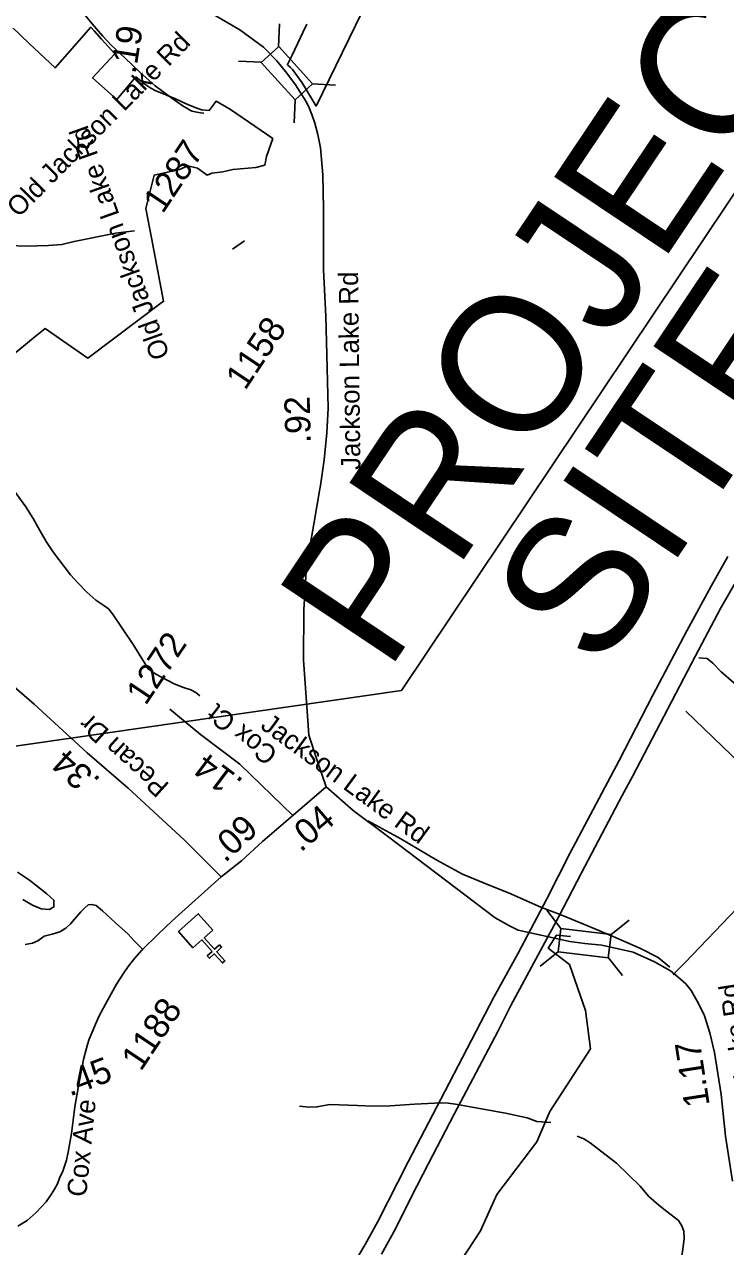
# Model space of a CAD drawing. Extents: x 1715610 to 1720914, y 798298 to 802505.
# Drawn here: x 1715979.8 to 1716054.7, y 799574.8 to 799705.3 of the extents above; entities that cross this region are included whole.
import ezdxf

# ---------------------------------------------------------------- set-up
doc = ezdxf.new("R2010")
doc.units = 0
doc.layers.add('Default', color=7, linetype='Continuous')
doc.layers.add('Prop DSN Text', color=7, linetype='Continuous')

msp = doc.modelspace()

# ---------------------------------------------------------------- linework, layer by layer
at = {"layer": 'Default'}
for p, q in [((1716006.94, 799702.94), (1716007.06, 799705.4)), ((1716005.12, 799701.29), (1716002.66, 799701.41)), ((1716013.05, 799698.85), (1716010.59, 799698.98)), ((1716008.61, 799694.83), (1716008.73, 799697.28)), ((1716002.03, 799681.34), (1716003.31, 799682.21)), ((1716012.04, 799623.88), (1716008.47, 799620.83)), ((1716037.02, 799610.25), (1716035.04, 799610.99)), ((1716035.59, 799610.71), (1716037.11, 799608.77)), ((1716042.47, 799608.12), (1716044.4, 799609.64)), ((1716034.88, 799604.75), (1716036.82, 799606.27)), ((1716042.17, 799605.68), (1716043.7, 799603.74))]:
    msp.add_line(p, q, dxfattribs=at)
for points in [[(1715984, 799710.04), (1715991.9, 799708.62), (1715997.87, 799707.36), (1715999.57, 799706.64), (1716002.83, 799704.77), (1716005.36, 799702.91), (1716006.78, 799701.45), (1716007.85, 799700.13)], [(1715984, 799710.04), (1715984.76, 799708.52), (1715985.92, 799706.77), (1715987.04, 799705.38), (1715988.17, 799704.06), (1715989.03, 799703.15), (1715990.57, 799701.72), (1715992.13, 799700.23), (1715993.78, 799698.78), (1715995.56, 799697.45), (1715996.77, 799696.6), (1715997.14, 799696.37), (1715997.47, 799696.18), (1715997.72, 799696.07), (1715998.06, 799695.98), (1715998.63, 799695.87), (1715998.96, 799695.84)], [(1716016.56, 799708.09), (1716010.96, 799696.6), (1716009.47, 799699.1), (1716008.43, 799700.5), (1716008.19, 799700.75), (1716007.95, 799700.99), (1716007.9, 799701.04), (1716008.39, 799702.06), (1716009.84, 799705.09), (1716009.96, 799705.33), (1716009.92, 799705.37)], [(1716016.56, 799708.09), (1716010.96, 799696.6), (1716009.47, 799699.1), (1716008.43, 799700.5), (1716008.19, 799700.75), (1716007.95, 799700.99), (1716007.9, 799701.04), (1716008.39, 799702.06), (1716009.84, 799705.09), (1716009.96, 799705.33), (1716009.92, 799705.37)], [(1715974.84, 799666.96), (1715980.75, 799671.8), (1715982.04, 799672.85), (1715983.93, 799671.53), (1715986.57, 799669.69), (1715994.67, 799675.76), (1715993.37, 799682.53), (1715992.78, 799685.66), (1715993.68, 799689.23), (1715996.38, 799689.83), (1715997.28, 799690.24), (1715998.3, 799689.98), (1715999.33, 799689.24), (1715999.84, 799689.46), (1716000.99, 799689.6), (1716002.07, 799689.83), (1716004.54, 799690.03), (1716005.47, 799690.31), (1716005.65, 799691.24), (1716006.34, 799693.14), (1716001.83, 799696.23), (1716000.28, 799697.13), (1715999.55, 799696.15), (1715998.74, 799696.19), (1715998.16, 799696.42), (1715997.34, 799696.74), (1715996.62, 799697.06), (1715995.79, 799697.44), (1715995.24, 799697.68), (1715994.68, 799697.91), (1715993.84, 799698.25), (1715993.3, 799698.52), (1715992.67, 799698.96), (1715992.07, 799699.43), (1715991.72, 799699.73), (1715989.67, 799697.3), (1715987.09, 799699.64), (1715989.45, 799702.19), (1715988.06, 799703.74), (1715987.26, 799704.64), (1715986.91, 799705.03), (1715984.37, 799702.15), (1715983.08, 799700.68), (1715980.31, 799703.3), (1715976.56, 799706.89)], [(1715974.84, 799666.96), (1715980.75, 799671.8), (1715982.04, 799672.85), (1715983.93, 799671.53), (1715986.57, 799669.69), (1715994.67, 799675.76), (1715993.37, 799682.53), (1715992.78, 799685.66), (1715993.68, 799689.23), (1715996.38, 799689.83), (1715997.28, 799690.24), (1715998.3, 799689.98), (1715999.33, 799689.24), (1715999.84, 799689.46), (1716000.99, 799689.6), (1716002.07, 799689.83), (1716004.54, 799690.03), (1716005.47, 799690.31), (1716005.65, 799691.24), (1716006.34, 799693.14), (1716001.83, 799696.23), (1716000.28, 799697.13), (1715999.55, 799696.15), (1715998.74, 799696.19), (1715998.16, 799696.42), (1715997.34, 799696.74), (1715996.62, 799697.06), (1715995.79, 799697.44), (1715995.24, 799697.68), (1715994.68, 799697.91), (1715993.84, 799698.25), (1715993.3, 799698.52), (1715992.67, 799698.96), (1715992.07, 799699.43), (1715991.72, 799699.73), (1715989.67, 799697.3), (1715987.09, 799699.64), (1715989.45, 799702.19), (1715988.06, 799703.74), (1715987.26, 799704.64), (1715986.91, 799705.03), (1715984.37, 799702.15), (1715983.08, 799700.68), (1715980.31, 799703.3), (1715976.56, 799706.89)], [(1716007.85, 799700.13), (1716008.76, 799698.86), (1716009.95, 799697.02), (1716010.23, 799696.41), (1716010.51, 799695.71), (1716010.84, 799694.78), (1716011.16, 799693.58), (1716011.42, 799692.15), (1716011.67, 799689.25), (1716011.75, 799685.64), (1716011.75, 799679.11), (1716011.99, 799674.17), (1716012.1, 799670.04), (1716012.24, 799664.35), (1716012.09, 799661.71), (1716011.82, 799658.82), (1716011.42, 799656.09), (1716011.34, 799655.51), (1716010.77, 799652.18), (1716009.93, 799647.45), (1716009.66, 799642.81), (1716009.62, 799637.46), (1716010.12, 799630.45), (1716010.19, 799629.42), (1716011.06, 799626.7), (1716012.04, 799623.88)], [(1715991.55, 799683.28), (1715989.54, 799683.03), (1715985.13, 799682.14), (1715983.82, 799681.83), (1715982.37, 799681.71), (1715981.18, 799681.67), (1715980, 799681.64), (1715978.17, 799681.73)], [(1716036.89, 799610.04), (1716039.32, 799614.69), (1716043.63, 799622.97), (1716044.75, 799625.01), (1716051.48, 799637.87), (1716054.16, 799642.95), (1716057.17, 799648.22), (1716059.03, 799651.06), (1716060.98, 799653.91), (1716062.54, 799656.07), (1716064.21, 799658.15), (1716065.88, 799660.11), (1716066.95, 799661.23), (1716069.27, 799663.67), (1716071.26, 799665.7), (1716071.99, 799666.34), (1716073.29, 799667.48), (1716074.26, 799668.3)], [(1715977.93, 799656.71), (1715978.93, 799655.23), (1715979.95, 799653.8), (1715980.75, 799652.57), (1715981.45, 799651.29), (1715982.12, 799650.11), (1715982.9, 799648.94), (1715984.73, 799646.53), (1715985.55, 799645.65), (1715986.49, 799644.7), (1715987.43, 799643.84), (1715988.29, 799643.25), (1715988.79, 799642.91), (1715989.21, 799642.36), (1715991.42, 799639.11), (1715992.82, 799636.84), (1715993.04, 799636.48), (1715993.83, 799635.94), (1715995.81, 799634.9), (1715996.8, 799634.49), (1715997.59, 799634.27), (1715998.12, 799633.96), (1715998.56, 799633.6)], [(1716014.52, 799572.21), (1716016.2, 799575.02), (1716017.53, 799577.4), (1716020.78, 799583.82), (1716024.71, 799591.36), (1716029.94, 799601.43), (1716032.55, 799606.11), (1716035.6, 799611.94), (1716038.09, 799616.83), (1716043.32, 799626.71), (1716046.93, 799633.67), (1716050.56, 799640.56), (1716053.15, 799645.31), (1716054.95, 799648.5)], [(1716000.83, 799614.29), (1715996.86, 799618.22), (1715990.88, 799623.76), (1715986.52, 799627.54), (1715980.85, 799632.71), (1715977.66, 799635.5), (1715973.98, 799639.15), (1715972.22, 799641.35)], [(1716051.83, 799637.68), (1716052.72, 799637.6), (1716053.34, 799637.12), (1716054.21, 799636.16), (1716055.55, 799635.03), (1716057.3, 799633.74), (1716059.46, 799632.26), (1716061.05, 799631.28), (1716062.17, 799630.67), (1716063.1, 799630.19), (1716063.93, 799629.94)], [(1716008.47, 799620.83), (1716002.8, 799626.33), (1715998.61, 799629.47), (1715995.33, 799632.18)], [(1716072.43, 799603.78), (1716068.96, 799606.8), (1716058.23, 799624.46), (1716050.43, 799631.98)], [(1716012.04, 799623.88), (1716014.93, 799621.35), (1716018.6, 799618.63), (1716030.1, 799609.9), (1716031.62, 799609.04), (1716032.55, 799608.59), (1716038.07, 799607.36), (1716039.67, 799607.17)], [(1716008.47, 799620.83), (1716005.25, 799618.05), (1716003.01, 799615.98), (1716000.83, 799614.29)], [(1716035.04, 799610.99), (1716031.76, 799612.46), (1716028.83, 799613.65), (1716026.59, 799614.57), (1716023.86, 799616.06), (1716020.01, 799618.34), (1716016.5, 799620.26)], [(1715979.66, 799611.85), (1715980.68, 799611.27), (1715981.61, 799610.85), (1715982.48, 799610.78), (1715982.97, 799611.06), (1715982.95, 799611.78), (1715982.2, 799612.48), (1715980.34, 799613.93), (1715979.08, 799614.77)], [(1716000.83, 799614.29), (1715997.34, 799611.14), (1715995.54, 799609.53), (1715994.08, 799608.16), (1715992.36, 799606.44), (1715991.55, 799605.57), (1715990.9, 799604.7), (1715990.44, 799604.03), (1715989.66, 799602.81), (1715988.67, 799601.06), (1715987.81, 799599.43), (1715987.41, 799598.54), (1715987.14, 799597.93), (1715986.74, 799596.95), (1715986.55, 799596.38), (1715986.43, 799595.97), (1715986.13, 799594.76), (1715985.59, 799591.95), (1715985.21, 799589.72), (1715984.85, 799586.85), (1715984.49, 799584.86), (1715984.31, 799584.02), (1715983.92, 799582.85), (1715983.57, 799582.1), (1715983.35, 799581.47), (1715983.01, 799580.9), (1715982.67, 799580.33), (1715982.13, 799579.58), (1715981.07, 799578.43), (1715980.11, 799577.56), (1715979.1, 799576.96)], [(1716049.1, 799603.8), (1716049.53, 799604.29), (1716050.36, 799605.14), (1716055.9, 799610.91), (1716056.92, 799611.83), (1716057.3, 799612.51), (1716057.32, 799612.7)], [(1715992.49, 799606.48), (1715991.53, 799607.46), (1715990.88, 799608.15), (1715989.55, 799609.38), (1715988.15, 799610.64), (1715987.48, 799611.23), (1715987.02, 799611.34), (1715986.62, 799611.28), (1715986.24, 799610.92), (1715985.85, 799610.53), (1715984.74, 799609.25), (1715984.24, 799608.8), (1715983.58, 799608.42), (1715982.78, 799608.15), (1715981.93, 799607.95), (1715981.23, 799607.43), (1715980.69, 799607.18), (1715979.9, 799607.05)], [(1716017.96, 799573.99), (1716019.44, 799576.68), (1716021.12, 799580.08), (1716022.95, 799583.65), (1716025.72, 799588.92), (1716030.36, 799597.77), (1716031.77, 799600.54), (1716036.89, 799610.04)], [(1716048.74, 799604.62), (1716047.5, 799605.66), (1716045.59, 799606.64), (1716042.7, 799607.9), (1716039.86, 799609.08), (1716037.02, 799610.25)], [(1716034.55, 799585.98), (1716035.93, 799589.21), (1716040.26, 799595.89), (1716039.73, 799599.99), (1716038.02, 799604.9), (1716035.76, 799606.65), (1716036.65, 799608.05), (1716038.12, 799607.9)], [(1716039.67, 799607.17), (1716041.46, 799606.97), (1716044.81, 799606.23), (1716047.11, 799605.19), (1716048.8, 799604.23), (1716049.63, 799603.57), (1716050.43, 799602.84), (1716051.01, 799602.13), (1716051.81, 799600.75), (1716052.43, 799599.42), (1716053.02, 799597.62), (1716053.52, 799595.51), (1716054.21, 799591.02), (1716054.67, 799586.59), (1716055.43, 799581.78)], [(1716036.04, 799588.03), (1716034.54, 799588.16), (1716033.5, 799588.55), (1716031.19, 799589.02), (1716025.84, 799589.99), (1716025.07, 799590.1), (1716024.31, 799590.14), (1716021.46, 799589.98), (1716018.86, 799589.81), (1716017.05, 799589.78), (1716015.37, 799589.87), (1716012.44, 799589.97), (1716011.05, 799589.71), (1716010.18, 799589.68), (1716009.19, 799589.77)], [(1716038.85, 799586.59), (1716039.56, 799586.31), (1716040.24, 799585.85), (1716043.05, 799583.71), (1716045.58, 799581.25), (1716046.51, 799580.14), (1716047.56, 799579.21), (1716048.41, 799578.53), (1716049.65, 799577.57), (1716050.01, 799577.01), (1716050.25, 799576.43), (1716050.27, 799575.62), (1716050.09, 799574.27), (1716049.8, 799572.46), (1716049.6, 799571.39), (1716049.42, 799569.98), (1716049.32, 799568.68), (1716049.38, 799567.22), (1716049.46, 799564.32), (1716049.48, 799562.2), (1716049.42, 799561.03), (1716049.18, 799559.45)], [(1716023.87, 799569.33), (1716028.52, 799576.48), (1716030.26, 799580.34), (1716034.55, 799585.98)]]:
    msp.add_lwpolyline(points, dxfattribs=at)
for points in [[(1716008.73, 799697.28), (1716005.11, 799701.28), (1716006.97, 799702.97), (1716010.59, 799698.98)], [(1715999.93, 799608.6), (1715999.01, 799607.77), (1716000.12, 799606.54), (1716000.63, 799607.01), (1716000.87, 799606.75), (1716000.35, 799606.28), (1716001.22, 799605.31), (1716000.96, 799605.08), (1716000.09, 799606.05), (1715999.57, 799605.59), (1715999.34, 799605.84), (1715999.86, 799606.31), (1715998.75, 799607.54), (1715997.81, 799606.7), (1715996.27, 799608.43), (1715998.38, 799610.33)], [(1716037.11, 799608.77), (1716042.47, 799608.13), (1716042.17, 799605.63), (1716036.82, 799606.27)]]:
    msp.add_lwpolyline(points, close=True, dxfattribs=at)
at = {"layer": 'Prop DSN Text'}
for q in [(1716073.54, 799714.06), (1715962.07, 799625.8)]:
    msp.add_line((1716020.09, 799634.2), q, dxfattribs=at)

# ---------------------------------------------------------------- texts
at = {"layer": 'Default'}
for s, height, rotation, p in [('.19', 2.719, 81.0142, (1715991.68, 799699.97)), ('Old Jackson Lake Rd', 2.0663, 45.2182, (1715979.19, 799684.62)), ('Old Jackson Lake Rd', 2.0663, 109.6728, (1715995.36, 799669.96)), ('1287', 2.719, 56.2051, (1715994.58, 799685.02)), ('Jackson Lake Rd', 2.0663, 90.7212, (1716015.7, 799657.75)), ('1158', 2.719, 56.2051, (1716003.39, 799666.16)), ('.92', 2.719, 91.4728, (1716010.4, 799660.61)), ('1272', 2.719, 56.2051, (1715992.76, 799632.49)), ('Cox Ct', 2.066, 141.7184, (1716007, 799627.67)), ('Pecan Dr', 2.066, 138.0142, (1715995.39, 799624.14)), ('Jackson Lake Rd', 2.0663, 323.8288, (1716004.91, 799630.2)), ('.34', 2.719, 137.6689, (1715988.06, 799624.69)), ('.14', 2.719, 143.1087, (1716003.32, 799624.6)), ('.04', 2.719, 40.5079, (1716009.32, 799616.84)), ('.09', 2.719, 42.8226, (1716001.24, 799615.71)), ('Jackson Lake Rd', 2.0663, 98.9245, (1716059.3, 799582.08)), ('1188', 2.719, 56.2051, (1715992.25, 799593.42)), ('1.17', 2.719, 98.7366, (1716053.01, 799589.9)), ('.45', 2.719, 20.6075, (1715984.66, 799590.8)), ('Cox Ave', 2.066, 84.2382, (1715986.4, 799580.03))]:
    msp.add_text(s, height=height, rotation=rotation, dxfattribs=at).set_placement(p)
at = {"layer": 'Prop DSN Text'}
for s, p in [('PROJECT ', (1716018.55, 799635.97)), ('SITE', (1716041.3, 799636.02))]:
    msp.add_text(s, height=14.701, rotation=56.2051, dxfattribs=at).set_placement(p)

doc.saveas('drawing.dxf')
